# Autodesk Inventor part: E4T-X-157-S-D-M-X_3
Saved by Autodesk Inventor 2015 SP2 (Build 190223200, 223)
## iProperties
Created: 2016-05
Part Number: E4T-X-157-S-D-M-X_3
Material: Allgemein
Document SubType Name: Modeling
Designer: ryll
Density: 1 g/cm^3
Appearance: Vorgabe
Author: ryll
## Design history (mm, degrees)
node "E4T-X-157-S-D-M-X_31"
node "E4T-X-157-S-D-M-X_3"
node "Basis1"
